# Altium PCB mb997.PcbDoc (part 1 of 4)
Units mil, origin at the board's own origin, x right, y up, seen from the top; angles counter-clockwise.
Board outline 2598.43 x 3818.9 mil, 2 copper layers (Top, Bottom), stack 62.402 mil thick; 205 components, 190 nets, 761 pads, 492 vias.
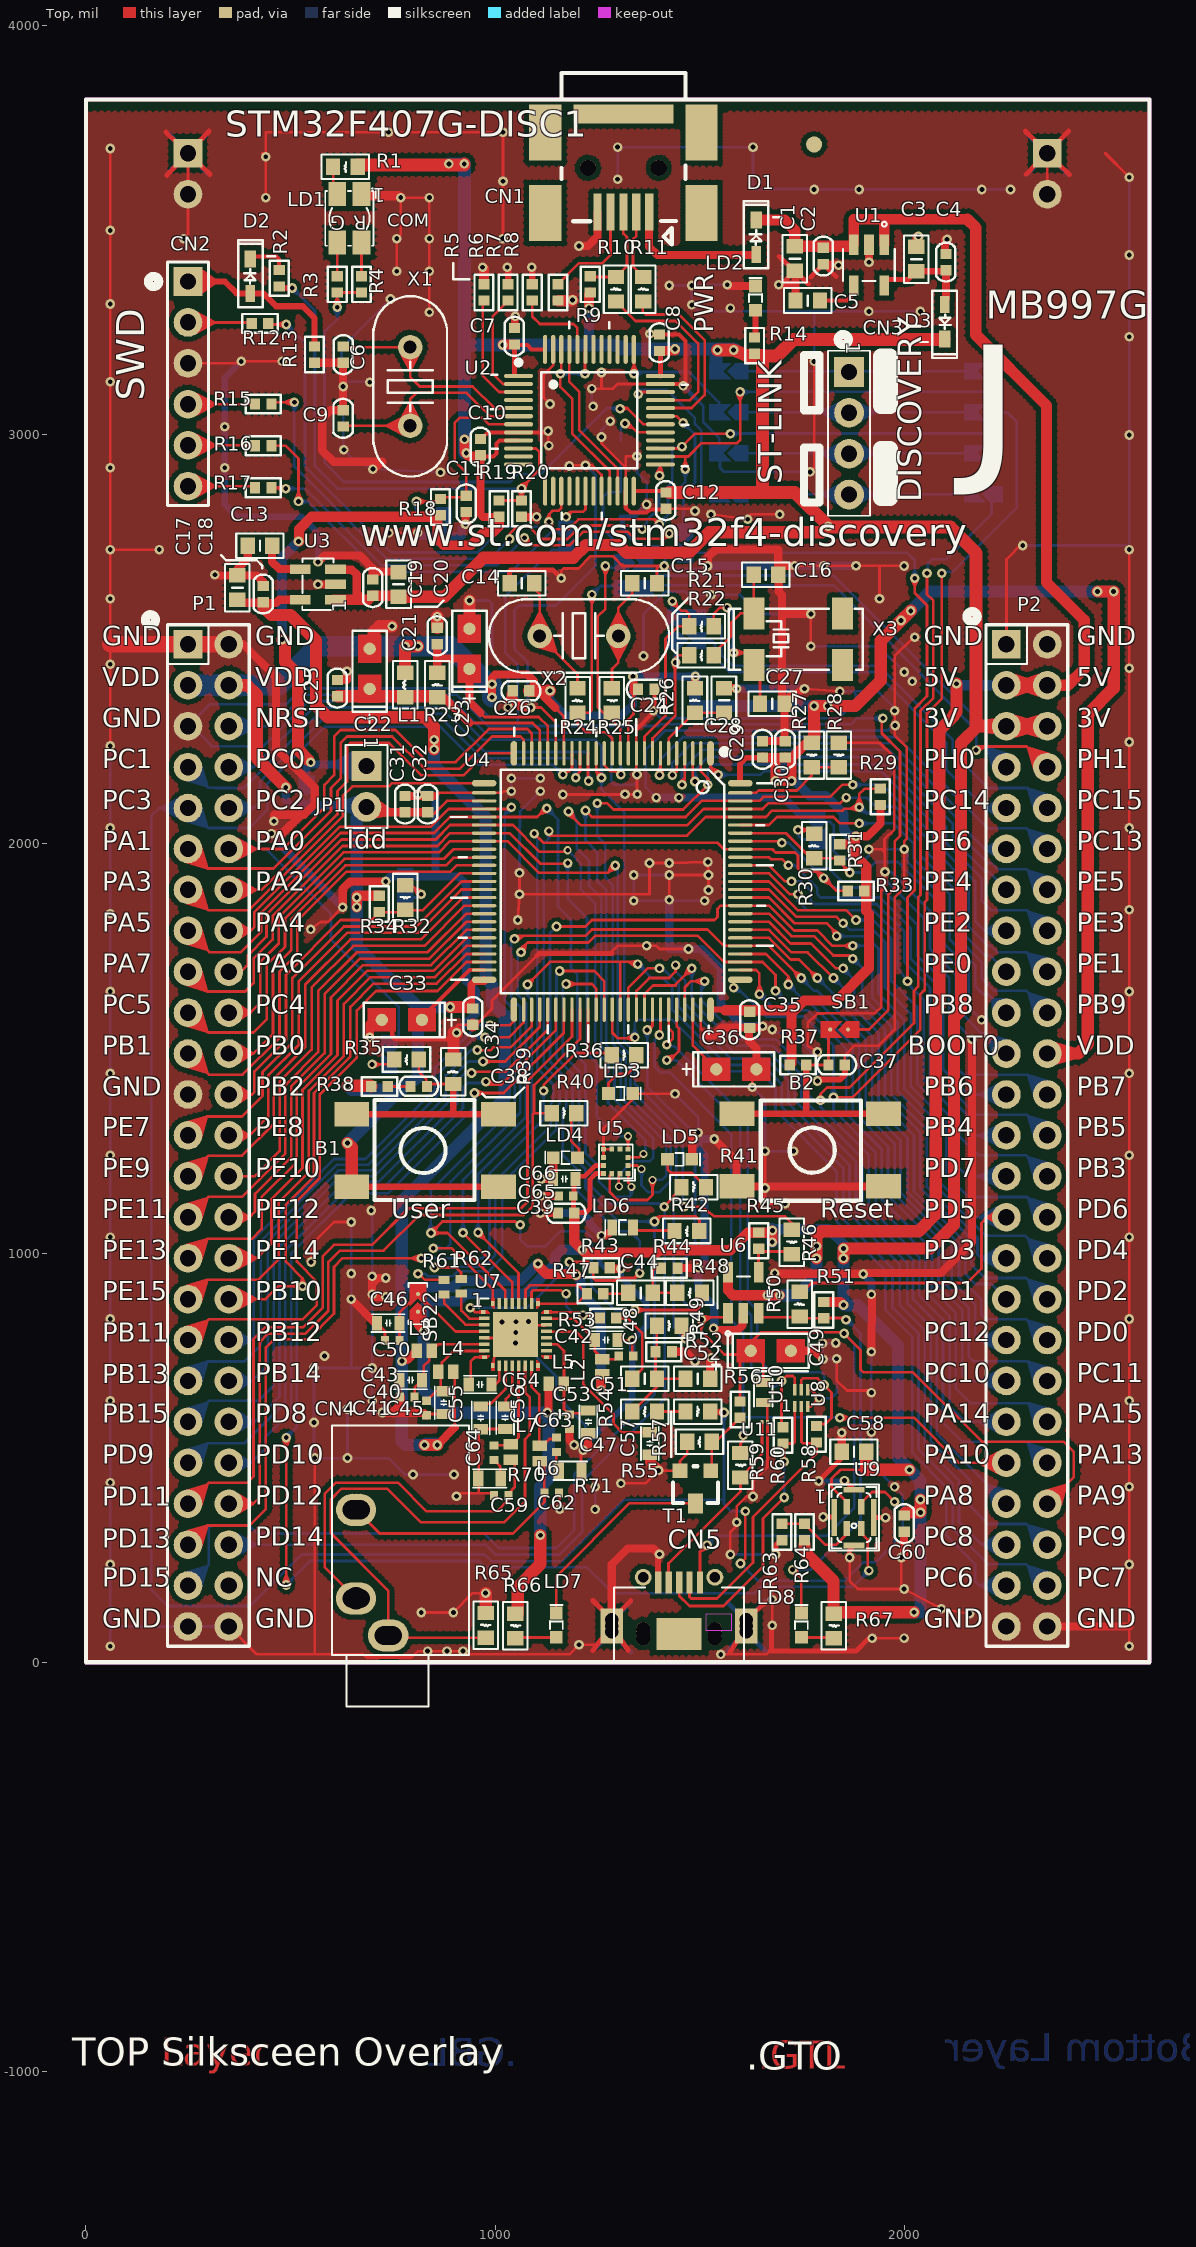
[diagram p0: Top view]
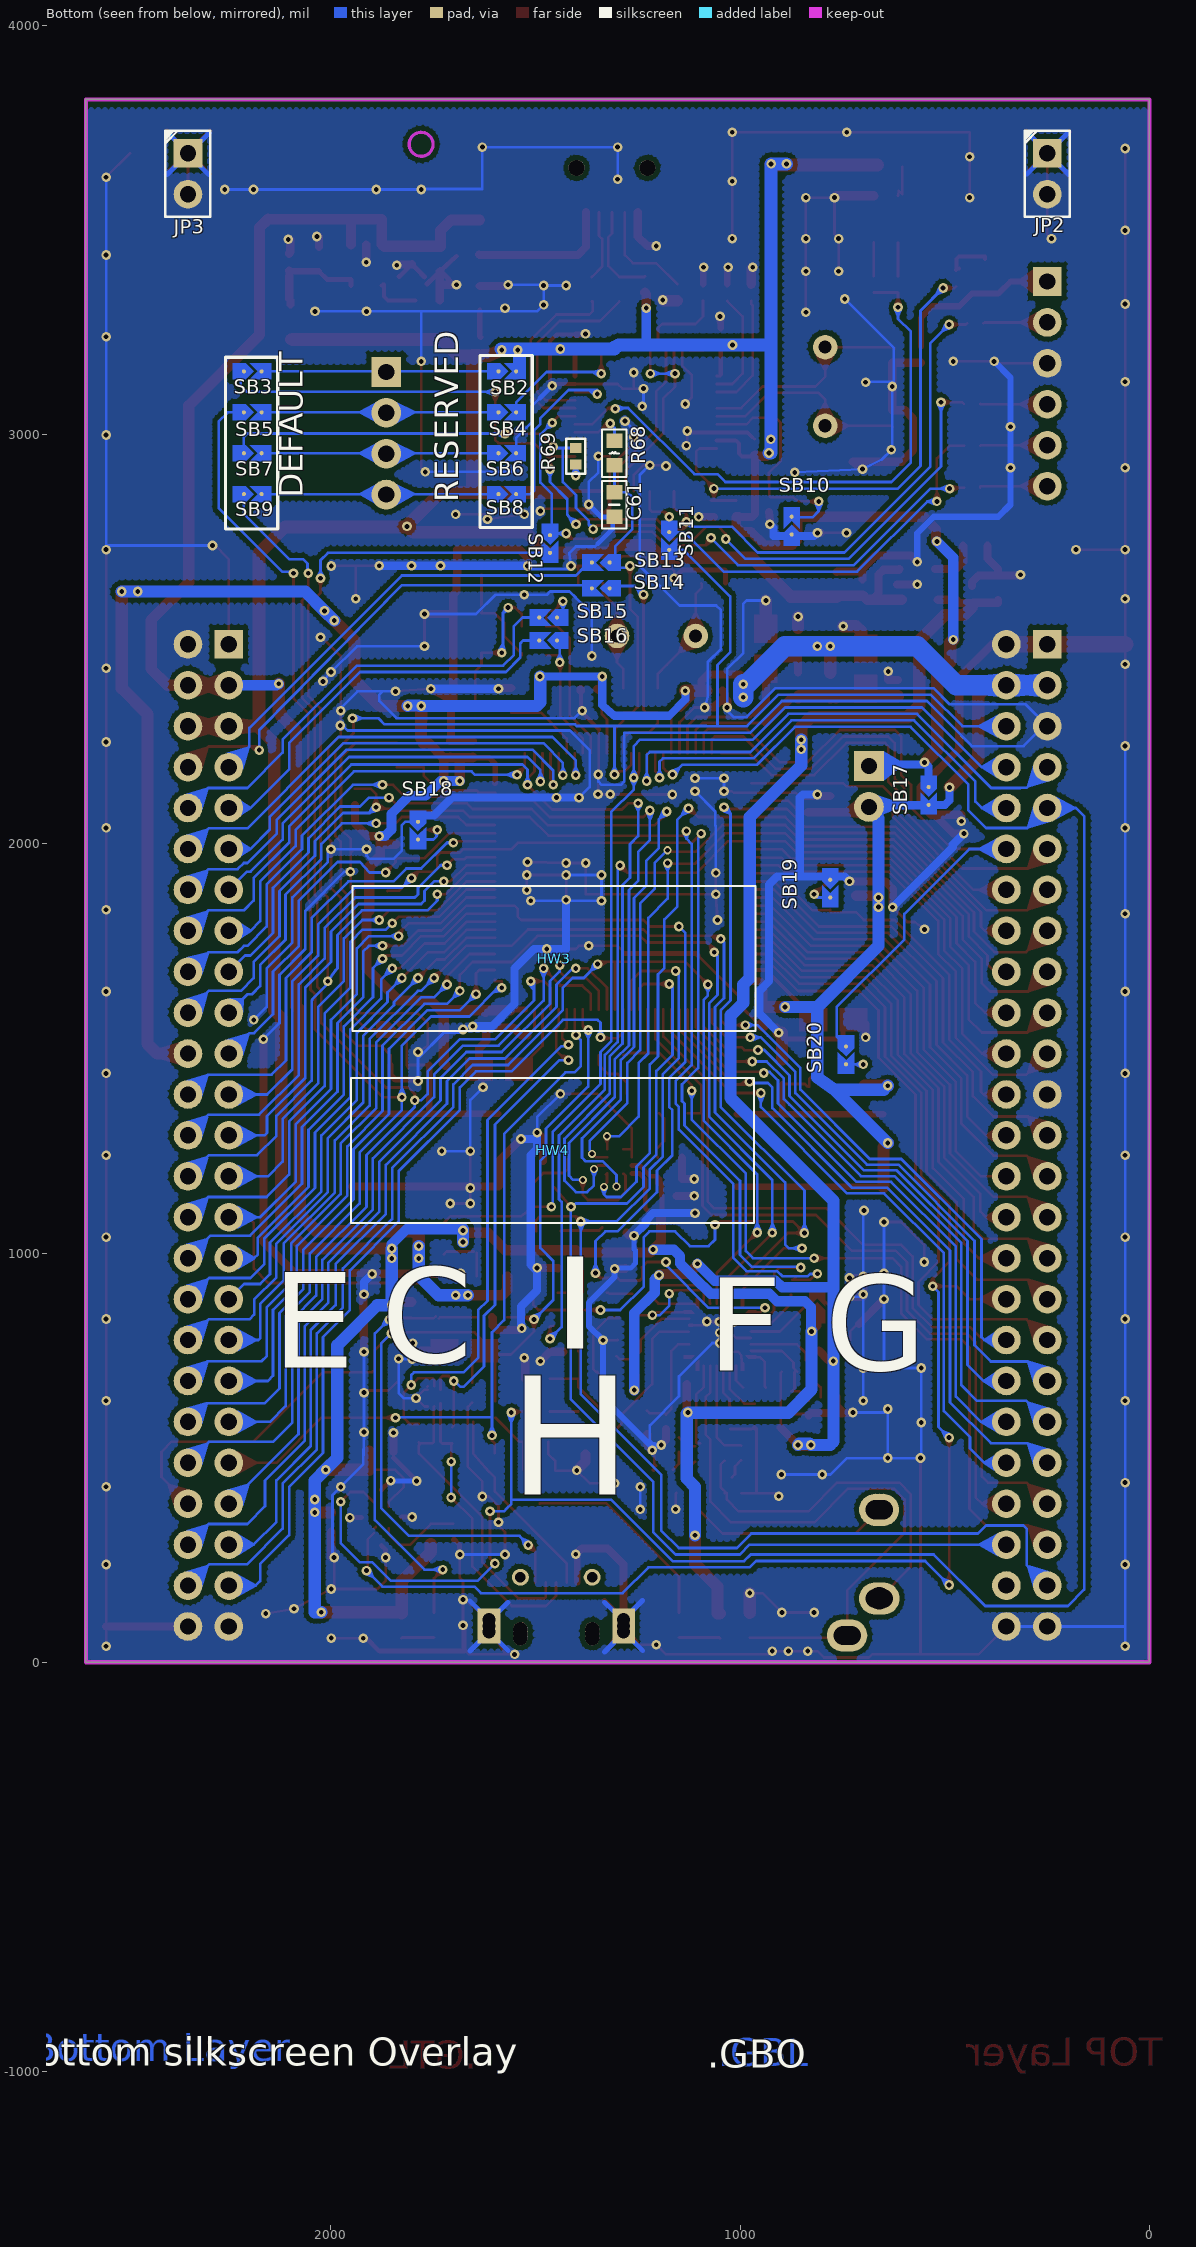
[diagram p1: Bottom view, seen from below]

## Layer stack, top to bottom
Solder Mask Top: solder mask 0.7874, Solder Resist, Dk 3.5
Top: signal copper 0.689
Dielectric 1: dielectric 61.0236, FR-4, Dk 4.2
Bottom: signal copper 0.689
Solder Mask Bottom: solder mask 0.7874, Solder Resist, Dk 3.5

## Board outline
0,0 2598.43,0 2598.43,3818.9 0,3818.9

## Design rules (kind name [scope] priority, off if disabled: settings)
Clearance Clearance_U7 [InComponent('U7')] p1: gap=6 ignorepadtopadclearanceinfootprint=TRUE except(3.94: Arc-Arc Arc-Track Track-Track; 5.12: Arc-Via Track-Via; 7: Track-Region SMDPad-Region; 9.84: Via-Fill Via-Poly Via-Region; 10: Text-Text; 11.81: Arc-Fill Arc-Poly Arc-Region Track-Fill Track-Poly; 12: SMDPad-Fill SMDPad-Poly THPad-Fill THPad-Poly THPad-Region Fill-Fill Fill-Poly Fill-Region Poly-Poly Poly-Region Region-Region)
Clearance Clearance_U5 [IsPad vs IsTrack] p2: gap=6 ignorepadtopadclearanceinfootprint=TRUE except(4.72: Arc-SMDPad Track-SMDPad; 10: Text-Text; 12: Arc-Fill Arc-Poly Arc-Region Track-Fill Track-Poly Track-Region SMDPad-Fill SMDPad-Poly SMDPad-Region THPad-Fill THPad-Poly THPad-Region Via-Fill Via-Poly Via-Region Fill-Fill Fill-Poly Fill-Region Poly-Poly Poly-Region Region-Region)
Clearance Clearance_CN5 [IsPad and ((Name = 'CN5-6') or (Name = 'CN5-6/2') or (Name = 'CN5-6/3') or (Name = 'CN5-6/4') or (Name = 'CN5-6/5') or (Name = 'CN5-6/6') or (Name = 'CN1-6') or (Name = 'CN1-7'))] p3: gap=6 ignorepadtopadclearanceinfootprint=TRUE except(5.98: Arc-Fill Arc-Poly Arc-Region Track-Fill Track-Poly Track-Region SMDPad-Fill SMDPad-Poly SMDPad-Region THPad-Fill THPad-Poly THPad-Region Via-Fill Via-Poly Via-Region Fill-Fill Fill-Poly Fill-Region Poly-Poly Poly-Region Region-Region; 10: Text-Text)
Clearance Clearance_JUMPER [HasFootprint('JUMPER') or HasFootprint('SOLDER-BRIDGE_R0603-0R') vs (HasFootprint('JUMPER')or HasFootprint('SOLDER-BRIDGE_R0603-0R') or IsTrack) and not InPolygon] p4: gap=6 ignorepadtopadclearanceinfootprint=FALSE except(5.91: Arc-Fill Arc-Poly Arc-Region Track-Fill Track-Poly Track-Region SMDPad-Fill SMDPad-Poly SMDPad-Region THPad-Fill THPad-Poly THPad-Region Via-Fill Via-Poly Via-Region Fill-Fill Fill-Poly Fill-Region Poly-Poly Poly-Region Region-Region; 10: Text-Text)
Clearance "Clearance - Default - DEFAULT- SMD" [IsVia vs IsSMTPin] p5 off: gap=6 ignorepadtopadclearanceinfootprint=FALSE
Clearance "Clearance - Default - DEFAULT - Via" [IsVia vs IsVia] p6 off: gap=6 ignorepadtopadclearanceinfootprint=FALSE
Clearance "Clearance - Default - DEFAULT - Net" [All] p7: gap=6 ignorepadtopadclearanceinfootprint=TRUE except(3.94: Arc-Arc Arc-Track Track-Track; 5.12: Arc-Via Track-Via; 9.84: Via-Fill Via-Poly Via-Region; 10: SMDPad-Region Text-Text; 11.81: Arc-Fill Arc-Poly Arc-Region Track-Fill Track-Poly Track-Region; 12: SMDPad-Fill SMDPad-Poly THPad-Fill THPad-Poly THPad-Region Fill-Fill Fill-Poly Fill-Region Poly-Poly Poly-Region Region-Region)
ComponentClearance "ComponentClearance - Default - DEFAULT" [All] p1: gap=6 collisioncheckmode=3 verticalgap=10 showdistances=FALSE
HoleToHoleClearance HoleToHoleClearance_CN5-6 [IsPad and ((Name = 'CN5-6') or (Name = 'CN5-6/2') or (Name = 'CN5-6/3') or (Name = 'CN5-6/4') or (Name = 'CN5-6/5') or (Name = 'CN5-6/6')) vs IsPad and ((Name = 'CN5-6') or (Name = 'CN5-6/2') or (Name = 'CN5-6/3') or (Name = 'CN5-6/4') or (Name = 'CN5-6/5') or (Name = 'CN5-6/6'))] p1: gap=0 allowstackedmicrovias=TRUE
HoleToHoleClearance HoleToHoleClearance_CN5-0 [IsPad and ((Name = 'CN5-0') or (Name = 'CN5-0/2') or (Name = 'CN5-0/6') or (Name = 'CN5-0/7') or (Name = 'CN5-0/8') or (Name = 'CN5-0/9') or (Name = 'CN5-0/11')) vs IsPad and ((Name = 'CN5-0') or (Name = 'CN5-0/2') or (Name = 'CN5-0/6') or (Name = 'CN5-0/7') or (Name = 'CN5-0/8') or (Name = 'CN5-0/9') or (Name = 'CN5-0/11'))] p2: gap=0 allowstackedmicrovias=TRUE
HoleToHoleClearance HoleToHoleClearance_CN4-3 [IsPad and ((Name = 'CN4-3') or (Name = 'CN4-3/2') or (Name = 'CN4-3/3')) vs IsPad and ((Name = 'CN4-3') or (Name = 'CN4-3/2') or (Name = 'CN4-3/3'))] p3: gap=0 allowstackedmicrovias=TRUE
HoleToHoleClearance HoleToHoleClearance_CN4-2 [IsPad and ((Name = 'CN4-2') or (Name = 'CN4-2/2') or (Name = 'CN4-2/3')) vs IsPad and ((Name = 'CN4-2') or (Name = 'CN4-2/2') or (Name = 'CN4-2/3'))] p4: gap=0 allowstackedmicrovias=TRUE
HoleToHoleClearance HoleToHoleClearance_CN4-1 [IsPad and ((Name = 'CN4-1') or (Name = 'CN4-1/2') or (Name = 'CN4-1/3')) vs IsPad and ((Name = 'CN4-1') or (Name = 'CN4-1/2') or (Name = 'CN4-1/3'))] p5: gap=0 allowstackedmicrovias=TRUE
HoleToHoleClearance "HoleToHoleClearance - Default - DEFAULT" [All] p6: gap=0 allowstackedmicrovias=TRUE
MaxMinImpedance "Default Impedance" [All] p1: minimum=50.00 maximum=150.0
MinimumSolderMaskSliver [All] p1: minsoldermaskwidth=3.94
PlaneConnect "Default PlaneConnect" [All] p1: planeconnectstyle=Relief reliefexpansion=20 reliefentries=4 reliefconductorwidth=11.81 reliefairgap=10
PolygonConnect PolygonConnect_Noyé [IsPad And (Layer = 'MultiLayer') And (PadShape_AllLayers = 'Round')] p1: connectstyle=Direct reliefconductorwidth=10 reliefentries=4 polygonreliefangle="90 Angle" airgapwidth=10
PolygonConnect "PolygonConnect - Default Pad" [All] p2: thpad.connectstyle=NoConnect thpad.reliefconductorwidth=11.81 thpad.reliefentries=4 thpad.polygonreliefangle="45 Angle" thpad.airgapwidth=12 smdpad.connectstyle=NoConnect smdpad.reliefconductorwidth=7.87 smdpad.reliefentries=4 smdpad.polygonreliefangle="45 Angle" smdpad.airgapwidth=12 via.connectstyle=Direct via.reliefconductorwidth=11.81 via.reliefentries=4 via.polygonreliefangle="45 Angle" via.airgapwidth=10
RoomDefinition U_USB_OTG_FS [InComponentClass('U_USB_OTG_FS')] p1: confinementstyle=ConfineIn formatcopy=TRUE lockcomponents=FALSE outline -10660.35,-8968.15 -8660.35,-8968.15 -8660.35,-7968.15 -10660.35,-7968.15
RoomDefinition U_Top [InComponentClass('U_Top')] p2: confinementstyle=ConfineIn formatcopy=TRUE lockcomponents=FALSE outline -10660.35,-8968.15 -8660.35,-8968.15 -8660.35,-7968.15 -10660.35,-7968.15
RoomDefinition U_STM32Fx [InComponentClass('U_STM32Fx')] p3: confinementstyle=ConfineIn formatcopy=TRUE lockcomponents=FALSE outline -10660.35,-8968.15 -8660.35,-8968.15 -8660.35,-7968.15 -10660.35,-7968.15
RoomDefinition U_ST_LINK [InComponentClass('U_ST_LINK')] p4: confinementstyle=ConfineIn formatcopy=TRUE lockcomponents=FALSE outline -10660.35,-8968.15 -8660.35,-8968.15 -8660.35,-7968.15 -10660.35,-7968.15
RoomDefinition "U_IO Peripherals" [InComponentClass('U_IO Peripherals')] p5: confinementstyle=ConfineIn formatcopy=TRUE lockcomponents=FALSE outline -10660.35,-8968.15 -8660.35,-8968.15 -8660.35,-7968.15 -10660.35,-7968.15
RoomDefinition U_Audio [InComponentClass('U_Audio')] p6: confinementstyle=ConfineIn formatcopy=TRUE lockcomponents=FALSE outline -10660.35,-8968.15 -8660.35,-8968.15 -8660.35,-7968.15 -10660.35,-7968.15
RoutingLayers "RoutingLayers - Default - DEFAULT" [All] p1: top layer_v5=TRUE bottom layer_v5=TRUE
RoutingPriority "RoutingPriority - Default - DEFAULT" [All] p1: routingpriority=3
RoutingTopology "Default Routing Topology" [All] p1: topology=Shortest
RoutingVias "RoutingVias - Default - DEFAULT" [All] p1: holewidth=11.81 width=23.62 viastyle="Through Hole" minholewidth=11.81 minwidth=23.62 maxholewidth=11.81 maxwidth=23.62
SMDToCorner "SMDToCorner - Default - DEFAULT" [All] p1: distance=0
ShortCircuit ShortCircuit_1 [IsPad and ((Name = 'CN5-6/2') or (Name = 'CN5-6/3') or (Name = 'CN5-6/5') or (Name = 'CN5-6') or (Name = 'CN5-6/4') or (Name = 'CN5-6/6')) vs IsPad and ((Name = 'CN5-6/2') or (Name = 'CN5-6/3') or (Name = 'CN5-6/5') or (Name = 'CN5-6') or (Name = 'CN5-6/4') or (Name = 'CN5-6/6'))] p1: allowed=TRUE
ShortCircuit ShortCircuit_CN5 [IsPad and ((Name = 'CN5-0') or (Name = 'CN5-0/2') or (Name = 'CN5-0/6') or (Name = 'CN5-0/7') or (Name = 'CN5-0/8') or (Name = 'CN5-0/9') or (Name = 'CN5-0/11')) vs IsPad and ((Name = 'CN5-0') or (Name = 'CN5-0/2') or (Name = 'CN5-0/6') or (Name = 'CN5-0/7') or (Name = 'CN5-0/8') or (Name = 'CN5-0/9') or (Name = 'CN5-0/11'))] p2: allowed=TRUE
ShortCircuit ShortCircuit_U7 [IsPad and (Name = 'U7-0') vs IsVia and (Net = 'GND')] p3: allowed=TRUE
ShortCircuit [All] p4: allowed=FALSE
SolderMaskExpansion SolderMaskExpansion_Via [IsVia] p1: expansion=-39.37 istentingtop=FALSE
SolderMaskExpansion "SolderMaskExpansion from CAM settings" [All] p2: expansion=2 istentingtop=FALSE
SupplyNets "Schematic Supply Nets_10" [InNet('MICVDD')] p1: voltage=0.000
SupplyNets "Schematic Supply Nets_9" [InNet('CPVDD')] p2: voltage=0.000
SupplyNets "Schematic Supply Nets_8" [InNet('AVDD')] p3: voltage=0.000
SupplyNets "Schematic Supply Nets_7" [InNet('DBVDD')] p4: voltage=0.000
SupplyNets "Schematic Supply Nets_4" [InNet('DCVDD')] p5: voltage=0.000
SupplyNets "Schematic Supply Nets_6" [InNet('1V8')] p6: voltage=0.000
SupplyNets "Schematic Supply Nets_5" [InNet('3V')] p7: voltage=0.000
SupplyNets "Schematic Supply Nets_3" [InNet('VDD')] p8: voltage=0.000
SupplyNets "Schematic Supply Nets_2" [InNet('GND')] p9: voltage=0.000
SupplyNets "Schematic Supply Nets_1" [InNet('U5V')] p10: voltage=0.000
SupplyNets "Schematic Supply Nets" [InNet('5V')] p11: voltage=0.000
Width "Default Width" [All] p1: maxlimit=78.74 minlimit=6.5 preferedwidth=6.5
22 further rules are at their usual default settings.

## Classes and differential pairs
component class U_USB_OTG_FS: C49 CN5 LD7 LD8 R45 R46 R50 R51 R56 R57 R58 R59 R60 R66 R67 T1 U6 U8 U10 U11
component class U_STM32Fx: C14 C15 C16 C21 C22 C23 C24 C25 C26 C27 C28 C29 C30 C31 C32 C33 C34 C35 C36 L1 R21 R22 R23 R24 R25 R26 R27 R28 R29 R30 R31 R32 R33 R34 SB13 SB14 SB15 SB16 SB18 SB19 U4 X2 X3
component class U_ST_LINK: C1 C2 C3 C4 C5 C6 C7 C8 C9 C10 C11 C12 C13 C17 C18 C19 C20 C61 CN1 CN2 CN3 D1 D2 D3 JP1 JP2 JP3 LD1 LD2 R1 R2 R3 R4 R5 R6 R7 R8 R9 R10 R11 R12 R13 R14 R15 R16 R17 R18 R19 R20 R68 R69 SB2 SB3 SB4 SB5 SB6 SB7 SB8 SB9 SB10 SB11 SB12 SB17 U1 U2 U3 X1
component class U_IO_Peripherals: B1 B2 C37 C38 C39 C65 C66 LD3 LD4 LD5 LD6 R35 R36 R37 R38 R39 R40 R41 R42 SB1 SB20 U5
component class U_Audio: C40 C41 C42 C43 C44 C45 C46 C47 C48 C50 C51 C52 C53 C54 C55 C56 C57 C58 C59 C60 C62 C63 C64 CN4 L2 L3 L4 L5 L6 L7 R43 R44 R47 R48 R49 R52 R53 R54 R55 R61 R62 R63 R64 R65 R70 R71 SB22 U7 U9
component class U_Top: HW3 HW4 P1 P2

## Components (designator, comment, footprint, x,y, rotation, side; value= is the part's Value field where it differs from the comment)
B1 "SW-PUSH-CMS" SW4SMD 825.21,1250.9 r180 top
B2 "SW-PUSH-CMS" SW4SMD 1773.21,1250.9 r0 top
C1 "1µF_X5R_0603" 0603C 1732.24,3429.96 r90 top value=1uF
C2 "100nF" 0402C 1801.71,3436.4 r90 top
C3 "1µF_X5R_0603" 0603C 2029.21,3428.9 r90 top value=1uF
C4 "100nF" 0402C 2101.71,3421.4 r270 top
C5 "10nF_X7R_0603" 0603C 1763.74,3327.6 r0 top value=10nF
C6 "20pF" 0402C 628.41,3195.5 r90 top
C7 "100nF" 0402C 1047.24,3240.16 r270 top
C8 "100nF" 0402C 1401.57,3224.41 r270 top
C9 "20pF" 0402C 628.41,3039.5 r270 top
C10 "100nF" 0402C 963.81,2969.3 r270 top
C11 "100nF" 0402C 929.13,2830.71 r90 top
C12 "100nF" 0402C 1417.32,2838.58 r270 top
C13 "10nF_X7R_0603" 0603C 425.2,2728.35 r0 top value=10nF
C14 "20pF" 0603C 1065.21,2636.9 r0 top
C15 "20pF" 0603C 1365.21,2636.9 r180 top
C16 "6.8pF" 0603C 1661.42,2657.48 r0 top
C17 "1µF_X5R_0603" 0603C 370.08,2625.98 r90 top value=1uF
C18 "100nF" 0402C 433.07,2610.24 r270 top
C19 "100nF" 0402C 700.79,2625.98 r270 top
C20 "1µF_X5R_0603" 0603C 763.78,2633.86 r270 top value=1uF
C21 "100nF" 0402C 858.27,2507.87 r270 top
C22 "1uF" CASE-A 693.22,2427.55 r90 top
C23 "1uF" CASE-A 937.01,2476.38 r90 top
C24 "100nF" 0402C 1369.21,2377.9 r0 top
C25 "100nF" 0402C 614.52,2380.33 r270 top
C26 "100nF" 0402C 1062.99,2374.02 r0 top
C27 "6.8pF" 0603C 1677.17,2342.52 r0 top
C28 "1uF" 0603C 1559.06,2350.39 r90 top
C29 "100nF" 0402C 1653.36,2230.8 r270 top
C30 "100nF" 0402C 1708.45,2230.8 r270 top
C31 "100nF" 0402C 779.79,2097.01 r270 top
C32 "100nF" 0402C 834.88,2097.01 r270 top
C33 "2.2uF" CASE-A 771.92,1569.72 r180 top
C34 "100nF" 0402C 945.06,1577.59 r90 top
C35 "100nF" 0402C 1621.88,1569.72 r270 top
C36 "2.2uF" CASE-A 1589.21,1448.9 r0 top
C37 "100nF" 0402C 1834.37,1459.54 r180 top
C38 "100nF" 0402C 813.21,1406.9 r180 top
C39 "100nF" 0402C 1173.29,1097.52 r0 top
C40 "100nF" C0402 785.27,647.58 r0 top
C41 "100nF" C0402 832.56,621.31 r90 top
C42 "4.7uF" C0603 1271.05,787.58 r180 top
C43 "4.7uF" C0603 793.32,689.19 r0 top
C44 "1uF(X7R)" 0603C 1355.2,902.6 r0 top value=1uF
C45 "4.7uF" C0603 874.23,634.29 r90 top
C46 "4.7uF" C0603 738.58,828.78 r0 top
C47 "4.7uF" C0603 1227.68,587.4 r90 top
C48 "100nF" C0402 1319.81,748.01 r180 top
C49 "4.7uF" CASE-A 1673.5,760.98 r0 top
C50 "100nF" C0402 748.34,785.7 r0 top
C51 "1uF(X7R)" 0603C 1365.2,692.6 r0 top value=1uF
C52 "10nF" 0603C 1495.2,692.6 r0 top
C53 "100nF" C0402 1181.16,587.4 r90 top
C54 "2.2uF" C0603 963.23,678.6 r0 top
C55 "2.2uF" C0603 964.69,597.19 r90 top
C56 "2.2uF" C0603 1024.25,597.45 r90 top
C57 "4.7uF" C0603 1377.95,534.47 r90 top
C58 "10uF" 0603C 1876.71,514.12 r0 top
C59 "470pF" C0402 1015.07,407.38 r180 top
C60 "100nF" 0402C 1999.21,338.9 r90 top
C61 "20pF" 0603C 1307.08,2828.92 r270 bottom
C62 "470pF" C0402 1137.99,414.14 r0 top
C63 "100nF" C0402 1149.21,531.55 r90 top
C64 "100nF" C0402 997.33,512.17 r90 top
C65 "100nF" C0402 1173.2,1139.61 r0 top
C66 "10uF" C0603 1168.79,1180.99 r0 top
CN1 "UBF-MINI5-03" USB-MINI-B-SMD-A_ 1313.35,3651.61 r0 top
CN2 "Header 6" HEADER6$2F$2.54 249.21,3374.02 r270 top
CN3 "Jumper_Header 4x1 fitted 1-2_3-4" CON_SAMTEC_TSW-104-07-G-S 1864.66,3003.22 r270 top
CN4 "ST-225-02" PCBCOMPONENT_1$2F$2_new_ 699.21,218.9 r90 top
CN5 "475900001" USB-MICRO-AB_new 1449.21,194.9 r90 top value=47590-0001
D1 "BAT60JFILM" SOD323$2F$A 1637.76,3524.45 r270 top
D2 "BAT60JFILM" SOD323$2F$A 401.57,3429.13 r270 top
D3 "BAT60JFILM" SOD323$2F$A 2098.39,3233.11 r90 top
HW3 "STICKER_BOARD_CPN" STICKER_25X9_ 1454.71,1719.25 r180 bottom
HW4 "STICKER_BOARD_REF" STICKER_25X9_ 1458.2,1250.69 r180 bottom
JP1 "Jumper_Header 2x1 Fitted" CON_SAMTEC_TSW-102-07-G-S 685.35,2140.24 r270 top
JP2 "" SIP2$2F$2.54 249.21,3637.4 r180 bottom
JP3 "" SIP2$2F$2.54 2349.21,3637.4 r180 bottom
L1 "fcm1608-0603" 0603L 779.79,2388.2 r270 top value=100uH
L2 "10R @100MHz" IND_0402_MURATA_BLM15H_H0P5 1261.43,721.93 r90 top
L3 "10R @100MHz" IND_0402_MURATA_BLM15H_H0P5 826.43,761.32 r0 top
L4 "10R @100MHz" IND_0402_MURATA_BLM15H_H0P5 879.18,710.17 r180 top
L5 "10R @100MHz" IND_0402_MURATA_BLM15H_H0P5 1149.21,680.03 r0 top
L6 "10R @100MHz" IND_0402_MURATA_BLM15H_H0P5 1109.33,510.4 r270 top
L7 "10R @100MHz" IND_0402_MURATA_BLM15H_H0P5 1037.56,513.82 r270 top
LD1 "LD_BICOLOR_CMS_1" LED_BI-GR_HSMF-A201-A00J1 643.66,3528.39 r180 top
LD2 "LED_red" LED_0603_RED 1636.12,3333.17 r90 top
LD3 "LED_orange" LED_0603_ORANGE_H0P4 1306.46,1389.76 r0 top
LD4 "LED_green" LED_0603_GREEN 1171.42,1232.9 r180 top
LD5 "LED_red" LED_0603_RED 1450.83,1229.04 r0 top
LD6 "LED_blue" LED_0603_SMD-B_BLUE_H0P4 1311.26,1062.75 r180 top
LD7 "LED_green" LED_0603_GREEN 1149.21,90.55 r90 top
LD8 "LED_red" LED_0603_RED 1748.03,90.55 r90 top
P1 "Header 25X2" HEAD25X2$2F$2.54 299.21,1287.4 r270 top
P2 "Header 25X2" HEAD25X2$2F$2.54 2299.21,1287.4 r270 top
R1 "0R" 0603R 633.82,3654.37 r0 top value=0
R2 "100" 0402R 472.44,3381.89 r270 top
R3 "560R" 0402R 614.13,3366.97 r90 top value=560
R4 "560R" 0402R 673.19,3366.97 r90 top value=560
R5 "10K" 0402R 972.4,3347.28 r270 top
R6 "10K" 0402R 1031.46,3347.28 r270 top
R7 "100K" 0402R 1090.51,3347.28 r270 top
R8 "100K" 0402R 1153.5,3347.28 r270 top
R9 "1K5" 0402R 1232.24,3366.97 r270 top
R10 "0" 0603R 1295.24,3355.16 r270 top
R11 "0" 0603R 1362.17,3355.16 r270 top
R12 "22" 0402R 425.2,3271.65 r0 top
R13 "10K" 0402R 558.21,3195.5 r270 top
R14 "1K" 0402R 1633.82,3217.36 r270 top
R15 "22" 0402R 433.07,3074.8 r0 top
R16 "22" 0402R 433.07,2972.44 r0 top
R17 "22" 0402R 433.07,2870.08 r0 top
R18 "100K" 0402R 866.14,2822.83 r270 top
R19 "4.7K" 0402R 1009.21,2818.9 r90 top
R20 "4.7K" 0402R 1064.09,2818.9 r90 top
R21 "0" 0603R 1503.94,2531.5 r0 top
R22 "0" 0603R 1503.94,2460.63 r0 top
R23 "47" 0603R 858.49,2388.2 r270 top
R24 "220" 0603R 1201.21,2349.9 r270 top
R25 "0" 0603R 1285.21,2349.9 r90 top
R26 "[N/A]" 0603R 1488.19,2350.39 r270 top value=0
R27 "[N/A]" 0603R 1773.21,2216.9 r90 top value=0
R28 "0" 0603R 1839.21,2216.9 r90 top
R29 "4.7K" 0402R 1941.21,2114.9 r90 top
R30 "510" 0603R 1779.28,1994.7 r270 top
R31 "10K" 0402R 1842.24,1978.96 r90 top
R32 "510" 0603R 779.79,1868.78 r90 top
R33 "4.7K" 0402R 1881.59,1884.52 r180 top
R34 "10K" 0402R 716.83,1853.04 r270 top
R35 "330" 0603R 783.21,1472.9 r0 top
R36 "680" 0603R 1314.95,1483.15 r180 top
R37 "1K5" 0402R 1739.93,1459.54 r180 top
R38 "100" 0402R 717.21,1406.9 r180 top
R39 "220K" 0603R 897.21,1442.9 r270 top
R40 "510" 0603R 1168.04,1341.61 r180 top
R41 "680" 0603R 1485.21,1160.9 r180 top
R42 "680" 0603R 1468.21,1053.9 r0 top
R43 "10K" 0402R 1259.86,963.73 r0 top
R44 "100K" 0402R 1425.2,962.6 r0 top
R45 "10K" 0402R 1644.21,1030.24 r270 top
R46 "0" 0603R 1724.19,1026.69 r90 top
R47 "100" 0402R 1244.12,900.77 r180 top
R48 "0" 0603R 1475.2,902.6 r0 top
R49 "0" 0603R 1425.13,822.07 r180 top
R50 "0" 0603R 1743.81,875.06 r270 top
R51 "47K" 0402R 1802.76,860.62 r270 top
R52 "100K" 0402R 1411.71,758.9 r0 top
R53 "100" 0402R 1275.59,841.18 r180 top
R54 "1.2K" 0603R 1365.2,612.6 r0 top
R55 "0" 0603R 1495.2,612.6 r180 top
R56 "47K" 0402R 1598.27,617.45 r90 top
R57 "[N/A]" 0603R 1499.21,538.9 r0 top value=1K
R58 "22R" 0402R 1784.91,557.15 r270 top value=47K
R59 "0R" 0603R 1599.21,481.4 r90 top value=0
R60 "22R" 0402R 1703.33,554.49 r270 top value=47K
R61 "0R" R0402 874.82,916.14 r90 top
R62 "0R" R0402 917.33,918.9 r90 top
R63 "0" 0402R 1700.58,318.39 r90 top
R64 "0" 0402R 1755.67,318.39 r270 top
R65 "0" 0603R 976.54,90.16 r90 top
R66 "330" 0603R 1049.21,88.9 r90 top
R67 "620" 0603R 1827.64,88.9 r90 top
R68 "100" 0603R 1307.08,2954.84 r270 bottom
R69 "100" 0402R 1401.52,2946.97 r90 bottom
R70 "20R" R0603 986.27,449.09 r0 top
R71 "20R" R0603 1183.15,467.86 r180 top
SB1 "Circuit Breaker" JUMPER 1842.24,1546.11 r180 top
SB2 "Circuit Breaker" JUMPER 1570.83,3154.37 r180 bottom
SB3 "Circuit Breaker" JUMPER 2192.87,3154.37 r180 bottom
SB4 "Circuit Breaker" JUMPER 1570.83,3054.37 r180 bottom
SB5 "Circuit Breaker" JUMPER 2192.87,3054.37 r180 bottom
SB6 "Circuit Breaker" JUMPER 1570.83,2954.37 r180 bottom
SB7 "Circuit Breaker" JUMPER 2192.87,2954.37 r180 bottom
SB8 "Circuit Breaker" JUMPER 1570.83,2854.37 r180 bottom
SB9 "Circuit Breaker" JUMPER 2192.87,2854.37 r180 bottom
SB10 "Circuit Breaker" JUMPER 874.02,2775.59 r90 bottom
SB11 "Circuit Breaker" JUMPER 1173.21,2741.9 r270 bottom
SB12 "Circuit Breaker" JUMPER 1464.48,2734.48 r270 bottom
SB13 "Circuit Breaker" JUMPER 1338.56,2687.26 r0 bottom
SB14 "Circuit Breaker" JUMPER 1338.56,2624.3 r0 bottom
SB15 "Circuit Breaker" JUMPER 1467.21,2552.9 r0 bottom
SB16 "Circuit Breaker" JUMPER 1467.21,2496.9 r0 bottom
SB17 "Circuit Breaker" JUMPER 539.21,2118.9 r270 bottom
SB18 "Circuit Breaker" JUMPER 1787.15,2034.05 r270 bottom
SB19 "Circuit Breaker" JUMPER 779.79,1892.39 r270 bottom
SB20 "Circuit Breaker" JUMPER 741.21,1484.9 r270 bottom
SB22 "0R" SOLDER-BRIDGE_R0603-0R 811.27,876.13 r90 top
T1 "9013" SOT23 1489.21,428.9 r180 top value=MMBT9013
U1 "LD3985M33R" SOT-23-5L 1913.35,3414.21 r0 top
U2 "STM32F103CBT6TR" LQFP48$2F$0.5MM$5C$9X9B 1118.11,2862.2 r0 top
U3 "LD3985M18R" REG_SOT23-5L 566.93,2633.86 r90 top
U4 "STM32F407VGT6" QFP100-1414 1285.96,1907.95 r180 top
U5 "IIS2DLPC" ICC_LGA12_2X2_P050_H0P7 1294.7,1223.9 r180 top
U6 "STMPS2141STR" SOT-23-5L 1606.24,903.26 r180 top
U7 "WM8904CGEFL/RV" ICC_QFN32-EPAD_4X4_P040 1049.4,800.74 r270 top
U8 "ECMF2-40A100N6" ESD_UQFN-6L_1P45X1P4_P040 1747.77,645.51 r0 top
U9 "CMM-4030DT-261075L-TR" MIC_SAME-SKY_CMM-4030DT-261075-TR 1876.71,353.34 r180 top
U10 "ESDA7P120-1U1M" ESD_QFN1610_2N_1K_2A 1654.68,658.9 r270 top
U11 "ESDZV5H-1BU2" ESD-BI_ST0201_H0P24 1658.5,587.4 r0 top
X1 "8MHz" HC-49A 792.21,3117.5 r90 top
X2 "8MHz" HC-49A 1204.72,2507.87 r0 top
X3 "MC306-G-06Q-32.768 (manufacturer JFVNY)" MC306-CRYSTAL 1740.16,2500 r0 top

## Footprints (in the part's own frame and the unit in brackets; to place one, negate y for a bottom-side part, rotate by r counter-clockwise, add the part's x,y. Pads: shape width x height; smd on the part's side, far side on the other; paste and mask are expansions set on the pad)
0402C [mil]
  rect 25x27.56 smd: 1(-20,0) 2(20,0)
  silkscreen extent -48,-24 47,23
0402R [mil]
  rect 25x27.56 smd: 1(-20,0) 2(20,0)
  silkscreen extent -43,-23 43,23
0603C [mil]
  rect 35x40 smd: 1(-30,0) 2(30,0)
  silkscreen extent -58,-30 58,30
0603L [mil]
  rect 35x40 smd: 1(-30,0) 2(30,0)
  silkscreen extent -58,-30 58,30
0603R [mil]
  rect 35x40 smd: 1(-30,0) 2(30,0)
  silkscreen extent -58,-30 58,30
C0402 [mm]
  rect 0.51x0.56 smd mask+0.05: 1(-0.45,0) 2(0.45,0)
  body extent -0.5,-0.3 0.5,0.3, height 0.4
C0603 [mm]
  rect 0.64x0.89 smd mask+0.05: 1(-0.7,0) 2(0.7,0)
  silkscreen extent -1.05,-0.55 1.02,0.55, body extent -0.9,-0.5 0.9,0.5, height 1.4
CASE-A [mil]
  round 30 smd: 1(-49,0) 2(49,0)
  Top region: -83,-28 -15,-28 -15,28 -83,28
  Top region: 15,-28 83,-28 83,28 15,28
  Top pour cut-out: -95.08,39.37 95.08,39.37 95.08,-39.96 -95.08,-39.96
  silkscreen extent -105,-42 93,42
CON_SAMTEC_TSW-102-07-G-S [mm]
  rect 1.85x1.85 / inner round 1.85 / far side rect 1.85x1.85 hole 1 mask+0.05: 1(-1.27,0)
  round 1.85 hole 1 mask+0.05: 2(1.27,0)
  silkscreen extent -2.58,-1.3 2.58,1.3, body extent -2.67,-1.3 2.58,1.3, height 8.38
CON_SAMTEC_TSW-104-07-G-S [mm]
  rect 1.85x1.85 / inner round 1.85 / far side rect 1.85x1.85 hole 1 mask+0.05: 1(-3.81,0)
  round 1.85 hole 1 mask+0.05: 2(-1.27,0) 3(1.27,0) 4(3.81,0)
  silkscreen extent -5.12,-1.3 5.12,1.3, body extent -5.21,-1.37 5.18,1.37, height 8.38
ESD-BI_ST0201_H0P24 [mm] "MCD-04846"
  rect 0.187x0.225 smd paste+0 mask+0.05: 1(-0.169,0) 2(0.169,0)
  body extent -0.31,-0.16 0.31,0.16, height 0.27
ESD_QFN1610_2N_1K_2A [mm] "DFN, 2-Leads, Body 1.60x1.00mm"
  rect 0.55x0.9 smd mask+0.05: 1(-0.625,0) 2(0.625,0)
  silkscreen extent -1.02,-0.58 0.85,0.58, body extent -0.85,-0.55 0.85,0.55, height 0.6
ESD_UQFN-6L_1P45X1P4_P040 [mm] "MCD-03060"
  rect 0.2x0.7 smd mask+0.05: 1(-0.4,-0.525) 2(0,-0.525) 3(0.4,-0.525) 4(0.4,0.525) 5(0,0.525) 6(-0.4,0.525)
  body extent -0.72,-0.7 0.72,0.7, height 0.51
HC-49A [mil]
  round 60 hole 32: 1(-96.06,0) 2(96.06,0)
  silkscreen extent -220,-90 220,90
HEAD25X2$2F$2.54 [mil]
  rect 70x70 hole 40: 1(-1200,-50)
  round 70 hole 40: 2(-1200,50) 3(-1100,-50) 4(-1100,50) 5(-1000,-50) 6(-1000,50) 7(-900,-50) 8(-900,50) 9(-800,-50) 10(-800,50) 11(-700,-50) 12(-700,50) 13(-600,-50) 14(-600,50) 15(-500,-50) 16(-500,50) 17(-400,-50) 18(-400,50) 19(-300,-50) 20(-300,50) 21(-200,-50) 22(-200,50) 23(-100,-50) 24(-100,50) 25(0,-50) 26(0,50) 27(100,-50) 28(100,50) 29(200,-50) 30(200,50) 31(300,-50) 32(300,50) 33(400,-50) 34(400,50) 35(500,-50) 36(500,50) 37(600,-50) 38(600,50) 39(700,-50) 40(700,50) 41(800,-50) 42(800,50) 43(900,-50) 44(900,50) 45(1000,-50) 46(1000,50) 47(1100,-50) 48(1100,50) 49(1200,-50) 50(1200,50)
  silkscreen extent -1248,-101 1248,100
HEADER6$2F$2.54 [mil]
  rect 70x70 hole 40: 1(0,0)
  round 70 hole 40: 2(100,0) 3(200,0) 4(300,0) 5(400,0) 6(500,0)
  silkscreen extent -48,-50 548,50
ICC_LGA12_2X2_P050_H0P7 [mm] "MCD-01448"
  rect 0.325x0.3 smd mask+0.05: 1(-0.763,0.75) 2(-0.763,0.25) 3(-0.763,-0.25) 4(-0.763,-0.75) 7(0.763,-0.75) 8(0.763,-0.25) 9(0.763,0.25) 10(0.763,0.75)
  rect 0.3x0.325 smd mask+0.05: 5(-0.25,-0.762) 6(0.25,-0.762) 11(0.25,0.763) 12(-0.25,0.763)
  silkscreen extent -1.2,-1.05 1.05,1.2, body extent -1.05,-1.05 1.05,1.05, height 0.71
ICC_QFN32-EPAD_4X4_P040 [mm]
  rect 0.22x0.3 smd mask+0.05: 1(-1.4,-2) 8(1.4,-1.925) 17(1.4,1.925) 24(-1.4,1.925)
  rect 0.22x0.66 smd mask+0.05: 2(-1,-1.925) 3(-0.6,-1.925) 4(-0.2,-1.925) 5(0.2,-1.925) 6(0.6,-1.925) 7(1,-1.925) 18(1,1.925) 19(0.6,1.925) 20(0.2,1.925) 21(-0.2,1.925) 22(-0.6,1.925) 23(-1,1.925)
  rect 0.3x0.22 smd mask+0.05: 9(1.925,-1.4) 16(1.925,1.4) 25(-1.925,1.4) 32(-1.925,-1.4)
  rect 0.66x0.22 smd mask+0.05: 10(1.925,-1) 11(1.925,-0.6) 12(1.925,-0.2) 13(1.925,0.2) 14(1.925,0.6) 15(1.925,1) 26(-1.925,1) 27(-1.925,0.6) 28(-1.925,0.2) 29(-1.925,-0.2) 30(-1.925,-0.6) 31(-1.925,-1)
  rect 2.8x2.8 smd mask+0.05: 33(0,0)
  Top region: 1.29,-2.255 1.29,-1.595 1.35,-1.595 1.51,-1.755 1.51,-2.255
  Top region: -1.29,-2.255 -1.29,-1.595 -1.35,-1.595 -1.51,-1.755 -1.51,-2.255
  Top region: -2.255,-1.29 -1.595,-1.29 -1.595,-1.35 -1.755,-1.51 -2.255,-1.51
  Top region: -2.255,1.29 -1.595,1.29 -1.595,1.35 -1.755,1.51 -2.255,1.51
  Top region: 2.255,1.29 1.595,1.29 1.595,1.35 1.755,1.51 2.255,1.51
  Top region: 2.255,-1.29 1.595,-1.29 1.595,-1.35 1.755,-1.51 2.255,-1.51
  Top region: 1.29,2.255 1.29,1.595 1.35,1.595 1.51,1.755 1.51,2.255
  Top region: -1.29,2.255 -1.29,1.595 -1.35,1.595 -1.51,1.755 -1.51,2.255
  silkscreen extent -2.25,-2.25 -1.68,-1.68, body extent -2.01,-2.01 2,2.01, height 0.91
IND_0402_MURATA_BLM15H_H0P5 [mm] "MCD-01610"
  rect 0.65x0.9 smd mask+0.05: 1(-0.475,0) 2(0.475,0)
  body extent -0.53,-0.28 0.53,0.28, height 0.55
JUMPER [mil]
  round 10 smd: 1(-19.68,0) 2(23.62,0)
  Top region: -47.24,-19.69 -47.24,19.68 -15.75,19.68 3.94,0 -15.75,-19.69
  Top region: -5.91,19.68 13.78,0 -5.91,-19.69 47.24,-19.69 47.24,19.68
  Top pour cut-out: -59.06,31.5 59.06,31.5 59.06,-31.5 -59.06,-31.5
LED_0603_GREEN [mm]
  rect 0.8x0.8 smd mask+0.05: 1(-0.75,0) 2(0.75,0)
  silkscreen extent -0.25,-0.4 1.25,0.4, body extent -0.8,-0.4 0.8,0.4, height 0.6
LED_0603_ORANGE_H0P4 [mm]
  rect 0.8x0.8 smd mask+0.05: 1(-0.75,0) 2(0.75,0)
  silkscreen extent -0.25,-0.4 1.25,0.4, body extent -0.8,-0.4 0.79,0.4, height 0.4
LED_0603_RED [mm]
  rect 0.8x0.8 smd mask+0.05: 1(-0.75,0) 2(0.75,0)
  silkscreen extent -0.25,-0.4 1.25,0.4, body extent -0.8,-0.4 0.8,0.4, height 0.6
LED_0603_SMD-B_BLUE_H0P4 [mm]
  rect 0.6x1 smd mask+0.05: 1(-0.65,0) 2(0.65,0)
  silkscreen extent -0.23,-0.45 1.07,0.45, body extent -0.85,-0.45 0.85,0.45, height 0.5
LED_BI-GR_HSMF-A201-A00J1 [mm] "MCD-00051"
  rect 1.1x1.5 smd mask+0.05: 1(-0.75,-1.5) 2(-0.75,1.5) 3(0.75,1.5) 4(0.75,-1.5)
  silkscreen extent -1.65,-1.85 1.5,1.7, body extent -1.5,-1.85 1.5,1.85, height 2.1
LQFP48$2F$0.5MM$5C$9X9B [mil]
  oval 71x10.13 smd: 1(-61,281.06) 12(-61,64.52) 25(285.46,64.53) 36(285.46,281.06)
  oval 71x10 smd: 2(-61,261.38) 3(-61,241.69) 4(-61,222.01) 5(-61,202.32) 6(-61,182.64) 7(-61,162.95) 8(-61,143.27) 9(-61,123.58) 10(-61,103.9) 11(-61,84.21) 26(285.46,84.21) 27(285.46,103.9) 28(285.46,123.58) 29(285.46,143.27) 30(285.46,162.95) 31(285.46,182.64) 32(285.46,202.32) 33(285.46,222.01) 34(285.46,241.69) 35(285.46,261.38)
  oval 10.13x71 smd: 13(3.96,-0.43) 24(220.5,-0.43) 37(220.5,346.02) 48(3.96,346.02)
  oval 10x71 smd: 14(23.65,-0.43) 15(43.33,-0.43) 16(63.02,-0.43) 17(82.7,-0.43) 18(102.39,-0.43) 19(122.07,-0.43) 20(141.76,-0.43) 21(161.44,-0.43) 22(181.13,-0.43) 23(200.81,-0.43) 38(200.81,346.02) 39(181.13,346.02) 40(161.44,346.02) 41(141.76,346.02) 42(122.07,346.02) 43(102.39,346.02) 44(82.7,346.02) 45(63.02,346.02) 46(43.33,346.02) 47(23.65,346.02)
  silkscreen extent -129,-69 354,414
MC306-CRYSTAL [mm]
  rect 1.3x2 smd: 1(-2.75,-1.6) 2(2.75,-1.6) 3(2.75,1.6) 4(-2.75,1.6)
  silkscreen extent -4.3,-1.9 4,1.9
MIC_SAME-SKY_CMM-4030DT-261075-TR [mm]
  rect 0.4x0.95 smd paste+0 mask+0.05: 1(0.45,-0.675) 2(0.45,0.675) 3(-0.45,0.675) 4(-0.45,-0.675)
  rect 0.35x2.3 smd paste+0 mask+0.05: 5(-1.225,0) 5(1.225,0)
  rect 1.3x0.35 smd paste+0 mask+0.05: 5(0,1.725) 5(0,-1.725)
  silkscreen extent -1.55,-2.05 1.55,2.05, body extent -1.45,-1.95 1.45,1.95, height 1.03
PCBCOMPONENT_1$2F$2_new_ [mm]
  round 2 hole 1.2: 1(-3.9,-1.254) 1(-3.9,-1) 1(-3.9,-0.746) 2(-1.6,0.746) 2(-1.6,1.254) 3(3.9,0.746) 3(3.9,1) 3(3.9,1.235)
  round 2 hole 1.4: 2(-1.6,1)
  silkscreen extent -8.31,-6 9.15,2.5
QFP100-1414 [mil]
  oval 16x60 smd: 1(-240.16,-312.99) 25(240.16,-312.99) 51(240.16,312.99) 75(-240.16,312.99)
  oval 8x60 smd: 2(-216.54,-312.99) 3(-196.85,-312.99) 4(-177.17,-312.99) 5(-157.48,-312.99) 6(-137.8,-312.99) 7(-118.11,-312.99) 8(-98.43,-312.99) 9(-78.74,-312.99) 10(-59.06,-312.99) 11(-39.37,-312.99) 12(-19.68,-312.99) 13(0,-312.99) 14(19.68,-312.99) 15(39.37,-312.99) 16(59.06,-312.99) 17(78.74,-312.99) 18(98.43,-312.99) 19(118.11,-312.99) 20(137.8,-312.99) 21(157.48,-312.99) 22(177.17,-312.99) 23(196.85,-312.99) 24(216.54,-312.99) 52(216.54,312.99) 53(196.85,312.99) 54(177.17,312.99) 55(157.48,312.99) 56(137.8,312.99) 57(118.11,312.99) 58(98.43,312.99) 59(78.74,312.99) 60(59.06,312.99) 61(39.37,312.99) 62(19.68,312.99) 63(0,312.99) 64(-19.68,312.99) 65(-39.37,312.99) 66(-59.06,312.99) 67(-78.74,312.99) 68(-98.43,312.99) 69(-118.11,312.99) 70(-137.8,312.99) 71(-157.48,312.99) 72(-177.17,312.99) 73(-196.85,312.99) 74(-216.54,312.99)
  oval 60x16 smd: 26(312.99,-240.16) 50(312.99,240.16) 76(-312.99,240.16) 100(-312.99,-240.16)
  oval 60x8 smd: 27(312.99,-216.54) 28(312.99,-196.85) 29(312.99,-177.17) 30(312.99,-157.48) 31(312.99,-137.8) 32(312.99,-118.11) 33(312.99,-98.43) 34(312.99,-78.74) 35(312.99,-59.06) 36(312.99,-39.37) 37(312.99,-19.69) 38(312.99,0) 39(312.99,19.68) 40(312.99,39.37) 41(312.99,59.06) 42(312.99,78.74) 43(312.99,98.43) 44(312.99,118.11) 45(312.99,137.8) 46(312.99,157.48) 47(312.99,177.17) 48(312.99,196.85) 49(312.99,216.54) 77(-312.99,216.54) 78(-312.99,196.85) 79(-312.99,177.17) 80(-312.99,157.48) 81(-312.99,137.8) 82(-312.99,118.11) 83(-312.99,98.43) 84(-312.99,78.74) 85(-312.99,59.06) 86(-312.99,39.37) 87(-312.99,19.68) 88(-312.99,0) 89(-312.99,-19.69) 90(-312.99,-39.37) 91(-312.99,-59.06) 92(-312.99,-78.74) 93(-312.99,-98.43) 94(-312.99,-118.11) 95(-312.99,-137.8) 96(-312.99,-157.48) 97(-312.99,-177.17) 98(-312.99,-196.85) 99(-312.99,-216.54)
  silkscreen extent -393,-396 394,392
R0402 [mm]
  rect 0.51x0.7 smd mask+0.05: 1(-0.45,0) 2(0.45,0)
  body extent -0.52,-0.3 0.52,0.3, height 0.4
R0603 [mm]
  rect 0.64x1 smd mask+0.05: 1(-0.7,0) 2(0.7,0)
  silkscreen extent -1.05,-0.58 1.05,0.58, body extent -0.9,-0.5 0.9,0.5, height 0.56
REG_SOT23-5L [mm]
  rect 0.6x1.3 smd mask+0.05: 1(-0.95,-1.1) 2(0,-1.1) 3(0.95,-1.1) 4(0.95,1.1) 5(-0.95,1.1)
  silkscreen extent -1.6,-0.95 1.6,0.97, body extent -1.52,-1.25 1.52,1.25, height 1.1
SIP2$2F$2.54 [mil]
  rect 70x70 / inner round 70 / far side rect 70x70 hole 40: 1(0,50)
  round 70 hole 40: 2(0,-50)
  silkscreen extent -55,-105 55,105
SOD323$2F$A [mm]
  rect 1.06x0.6 smd: 1(2.14,0)
  rect 1.06x0.7 smd: 2(0,0)
  silkscreen extent -1.17,-0.76 3,0.76
SOLDER-BRIDGE_R0603-0R [mil]
  round 10 smd mask-99999: 1(-19.69,0)
  round 10 smd paste-393.7: 2(23.62,0)
  Top region: -5.91,19.68 13.78,0 -5.91,-19.68 47.24,-19.68 47.24,19.68 -5.91,19.68
  Top region: -47.24,-19.68 -47.24,19.68 -15.75,19.68 3.94,0 -15.75,-19.68 -47.24,-19.68
  silkscreen extent -50,-23 50,23, body extent -36,-20 36,20, height 22
SOT23 [mil]
  rect 36x36 smd: 1(-37.5,-39) 2(37.5,-39)
  rect 36x50 smd: 3(0,41)
  silkscreen extent -55,-50 55,40
SOT-23-5L [mil]
  rect 23.62x50 smd: 1(37.4,50) 2(0,50) 3(-37.4,50) 4(-37.4,-50) 5(37.4,-50)
  silkscreen extent -63,-39 63,106
STICKER_25X9_ [mil] "Sticker 25mm x 9mm"
  silkscreen extent -492,-177 492,177
SW4SMD [mil]
  rect 85x60 smd: 1(175.59,-88.19) 2(-182.68,-88.19) 3(175.59,88.98) 4(-182.68,88.98)
  silkscreen extent -124,-123 121,122
USB-MICRO-AB_new [mm]
  round 1.4 hole 0.83: 0(-3.055,4.175) 0(-3.055,-4.175) 0(-2.7,4.175) 0(-2.7,-4.175) 0(-2.315,4.175) 0(-2.315,-4.175)
  rect 2.2x1.4 hole 0.83: 0(-2.7,4.175) 0(-2.7,-4.175)
  round 1.05 hole 0.65: 0/3(0.325,-2.225) 0/4(0.325,2.225)
  rect 2x2.8 smd: 0/5(-3.2,0)
  rect 1.35x0.4 smd: 1(0,-1.3) 2(0,-0.65) 3(0,0) 4(0,0.65) 5(0,1.3)
  round 0.9 hole 0.9 unplated: 6(-2.9,-2.225) 6/2(-3.175,2.225) 6/3(-2.9,2.225) 6/4(-3.45,-2.225) 6/5(-3.45,2.225) 6/6(-3.175,-2.225)
  silkscreen extent -4.9,-4.03 -0.3,4.03
USB-MINI-B-SMD-A_ [mm]
  rect 0.508x2.3 smd: 1(1.597,-2.75) 2(0.797,-2.75) 3(-0.003,-2.75) 4(-0.803,-2.75) 5(-1.603,-2.75)
  round 1 hole 1 unplated: 6(2.194,0) 7(-2.2,0)
  rect 2x3.5 smd: 8(-4.853,-2.8) 9(4.847,-2.8) 10(4.847,2.2) 11(-4.853,2.2)
  rect 6.2x1.2 smd: 12(0,3.35)
  silkscreen extent -3.85,-4.76 3.85,5.9

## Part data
B1: library part SW-PUSH-CMS_NEW, "Non-Open Push-Button 0.1A 24V", Manuf_1=CHAU-HUA, Manuf_Part_1=CTSM-644B-V-T/R
B2: library part SW-PUSH-CMS_NEW, "Non-Open Push-Button 0.1A 24V", Manuf_1=CHAU-HUA, Manuf_Part_1=CTSM-644N-V-T/R
C1 C3 C17 C20: library part "CAP SMD 0603  X5R 1µF 25V 10%", "0603  X5R 1µF", Manuf_1=YAGEO, Manuf_Part_1=CC0603KRX5R7BB105, Rated voltage=25V, Temperature Max=+125°C, Temperature Min=-55°C, Tolerance=10%
C2 C4 C7 C8 C10 C11 C12 C18 C19 C21 C24 C25 C26 C29 C30 C31 C32 C34 C35: library part Cap, "Capacitor", Manuf_1=YAGEO, Manuf_Part_1=CC0402KRX7R7BB104
C5 C13: library part "CAP SMD 0603  X7R 10000PF 50V 10%", "0603  X7R 10NF", Manuf_1=YAGEO, Manuf_Part_1=CC0603KRX7R9BB103, Rated voltage=50V, Temperature Max=+125°C, Temperature Min=-55°C, Tolerance=10%
C6 C9: library part Cap, "Capacitor", Manuf_1=YAGEO, Manuf_Part_1=CC0402JRNPO9BN200
C14 C15: library part CAP, "Capacitor", Manuf_1=YAGEO, Manuf_Part_1=CC0603JRNPO9BN200
C16 C27 C38: library part CAP, "Capacitor"
C22 C23: library part "Cap Pol1", "Polarized Capacitor (Radial)", Manuf_1=AVX, Manuf_Part_1=TAJA105K016R
C28 C44 C51: library part CAP, "Capacitor", Manuf_1=YAGEO, Manuf_Part_1=CC0603KRX5R7BB105
C33 C36: library part "Cap Low ESR", "Low ESR Ceramic Capacitor (X7R)", Manuf_1=YAGEO, Manuf_Part_1=CC1206KKX7R7BB225
C37 C39 C60: library part CAP, "Capacitor", Manuf_1=YAGEO, Manuf_Part_1=CC0402KRX7R7BB104
C40 C41 C48 C50 C53 C63 C64 C65: library part CC0402KRX7R7BB104, "Capacitor, MLCC, 100nF, 16V, X7R, +/-10%, 0402, T=0.5mm"
C42 C43 C45 C46 C47 C57: library part CC0603KRX5R7BB475, "Capacitor, MLCC, 4.7uF, 16V, X5R, +/-10%, 0603, T=0.8mm"
C49: library part "Cap Pol1", "Polarized Capacitor (Radial)", Manuf_1=AVX, Manuf_Part_1=TAJA475K016R
C52: library part CAP, "Capacitor", Manuf_1=YAGEO, Manuf_Part_1=CC0603KRX7R9BB103
C54 C55 C56: library part CC0603KRX5R6BB225, "Capacitor, MLCC, 2.2uF, 10V, X5R, +/- 10%, 0603, T=0.8mm"
C58: library part CAP, "Capacitor", Manuf_1=YAGEO, Manuf_Part_1=CC0603KRX5R5BB106
C59 C62: library part CC0402JRNPO9BN471, "Capacitor, MLCC, 470pF, 50V, C0G/NP0, +/-5%, 0402, T=0.5mm"
C61: library part Cap, "Capacitor"
C66: library part CC0603KRX5R5BB106, "Capacitor, MLCC, 10uF, 6V3, X5R, +/-10%, 0603, T=0.8mm"
CN1: library part "USB-MINI-typeB connector_", Manuf_1=MTCONN
CN2: "Header, 6-Pin", Manuf_1=LYCN, Manuf_Part_1=313106S141116
CN4: library part ST-225-02_, "Connector Jack 35mm", Manuf_1="XIEJIA Electronics"
CN5: library part 475900001_, Manuf_1=Molex, Manuf_Part_1=47590-0001
D1 D2 D3: Manuf_1=STM
JP2 JP3: library part JP2, Manuf_1=LYCN, Manuf_Part_1=313102S141145
L1: library part Inductor, "Inductor", Manuf_1=Tai-tech, Manuf_Part_1=FCM1608KF-601T03
L2 L3 L4 L5 L6 L7: library part BLM15AX100SN1D, "Ferrite bead, 10R @100MHz, 1.74A, 0.015R, 0402"
P1 P2: "Header, 25-Pin, Dual row", Manuf_1=LYCN, Manuf_Part_1=313250S141145
R1 R10 R11 R26 R48 R49 R55 R65: library part res1, "Resistor", Manuf_1=YAGEO, Manuf_Part_1=RC0603JR-070RL
R2 R57 R64: library part res1, "Resistor"
R3 R4: library part res1, "Resistor, 560R, 0402, +/-1%, 1/16W", Manuf_1=YAGEO, Manuf_Part_1=RC0402FR-07560RL
R5 R6 R13 R31 R34 R43 R45: library part res1, "Resistor", Manuf_1=YAGEO, Manuf_Part_1=RC0402FR-0710KL
R7 R8 R18 R44 R52: library part res1, "Resistor", Manuf_1=YAGEO, Manuf_Part_1=RC0402FR-07100KL
R9 R37: library part res1, "Resistor", Manuf_1=YAGEO, Manuf_Part_1=RC0402FR-071K5L
R12 R15 R16 R17: library part res1, "Resistor", Manuf_1=YAGEO, Manuf_Part_1=RC0402FR-0722RL
R14: library part res1, "Resistor", Manuf_1=YAGEO, Manuf_Part_1=RC0402FR-071KL
R19 R20 R29 R33: library part res1, "Resistor", Manuf_1=YAGEO, Manuf_Part_1=RC0402FR-074K7L
R21 R22 R27: library part Res1, "Resistor"
R23: library part Res1, "Resistor", Manuf_1=YAGEO, Manuf_Part_1=RC0603FR-0747RL
R24: library part Res1, "Resistor", Manuf_1=YAGEO, Manuf_Part_1=RC0603FR-07220RL
R25 R28 R46 R50 R59: library part Res1, "Resistor", Manuf_1=YAGEO, Manuf_Part_1=RC0603JR-070RL
R30 R40: library part Res1, "Resistor", Manuf_1=YAGEO, Manuf_Part_1=RC0603FR-07510RL
R32: library part res1, "Resistor", Manuf_1=YAGEO, Manuf_Part_1=RC0603FR-07510RL
R35 R66: library part res1, "Resistor", Manuf_1=YAGEO, Manuf_Part_1=RC0603FR-07330RL
R36 R41 R42: library part Res1, "Resistor", Manuf_1=YAGEO, Manuf_Part_1=RC0603FR-07680RL
R38 R47 R53 R69: library part res1, "Resistor", Manuf_1=YAGEO, Manuf_Part_1=RC0402FR-07100RL
R39: library part res1, "Resistor", Manuf_1=YAGEO, Manuf_Part_1=RC0603FR-07220KL
R51 R56: library part res1, "Resistor", Manuf_1=YAGEO, Manuf_Part_1=RC0402FR-0747KL
R54: library part res1, "Resistor", Manuf_1=YAGEO, Manuf_Part_1=RC0603FR-071K2L
R58 R60: library part RC0402FR-0722RL, "Resistor, 22R, 0402, +/-1%, 1/16W"
R61 R62: library part RC0402JR-070RL, "Resistor, 0R, 0402, +/-5%, 1/16W"
R63: library part res1, "Resistor", Manuf_1=YAGEO, Manuf_Part_1=RC0402JR-070RL
R67: library part Res1, "Resistor", Manuf_1=YAGEO, Manuf_Part_1=RC0603FR-07620RL
R68: library part res1, "Resistor", Manuf_1=YAGEO, Manuf_Part_1=RC0603FR-07100RL
R70 R71: library part RC0603FR-0720RL, "Resistor, 20R, 0603, +/-1%, 1/10W"
SB22: library part SB_ON, "Resistor, 0R, SB0603, 5%, 0.1W"
T1: library part NPN_NEW, "NPN Bipolar Transistor", Manuf_1=unisonic, Manuf_Part_1=MMBT9013
U1: "Ultra low drop-low noise BiCMOS voltage, regulators low ESR capacitors compatible", Manuf_1=STM
U2: library part STM32F103CBT6, "Medium-density performance line ARM-based 32-bit MCU with 128KB Flash", Manuf_1=STM
U4: "STM32 Manta (STM32F407VGT6)", Manuf_1=STM
U5: library part IC_IIS2DLPC
U6: "Enhanced single channel power switches", Manuf_1=STM
U7: library part IC_WM8904CGEFL/RV
U9: library part IC_CMM-4030DT-261075-TR, "MEMS Microphone, Top port, -26 ±1 dB, 2V6"
U10: library part ESD-TRANSIL, "Diode, ESD TVS, 5V5, 1.5uA, 6V8, QFN1610"
U11: library part ESD-TRANSIL-BIDIR, "Diode, ESD TVS, 5V5, 50nA, 10V, 0201"
X1 X2: library part XTAL, "Crystal Oscillator", Manuf_1=jfvny, Manuf_Part_1=HC-49S-C20QSA-8.000MHZ
X3: library part MC306

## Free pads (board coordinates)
  round 20 on Mech16: 1(403.98,-1259.28) 1(2303.7,-1265.01)
  round 39.37 smd mask+0: ""(1779.21,3708.9)

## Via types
v1: diameter 23.62, hole 11.81, Top to Bottom, 485 vias
v2: diameter 19.68, hole 11.81, Top to Bottom, 7 vias

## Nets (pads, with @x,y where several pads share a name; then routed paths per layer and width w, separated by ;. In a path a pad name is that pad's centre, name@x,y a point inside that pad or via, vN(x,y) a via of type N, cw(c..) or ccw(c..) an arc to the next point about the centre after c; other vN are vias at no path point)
1V8: C17.1 C18.2 L2.1 L3.1 L4.1 U3.5 | length 3995.5
  Top w6.5: C17.1@370.08,2595.98 433.07,2595.98 C18.2@433.07,2590.24 ; v1(772.22,735.79) v1@775.49,739.07 ; L4.1@897.88,710.17 900.9,707.15 900.9,573.29 ; L2.1@1258.53,700.32 L2.1@1261.43,703.22
  Top w20: C17.1@370.08,2595.98 370.08,2588.58 C18.2@442.91,2588.58 ; C18.2@433.07,2578.74 C18.2@442.91,2588.58 ; U3.5@516.93,2596.46 472.44,2596.46 464.57,2588.58 C18.2@442.91,2588.58 ; v1@775.49,739.07 785.47,739.07 L3.1@807.73,761.32 ; v1(858.49,530.88) 900.9,573.29
  Top w25: v1(1104.41,973.6) 1104.41,970.08 1126.01,948.47 1195.7,948.47 v1(1198.24,945.93) ; v1(1258.53,664.91) L2.1@1258.53,700.32
  Top w30: C18.2@433.07,2578.74 452.76,2559.06 500,2559.06 562.18,2496.87 562.18,2337.87 590.55,2309.5 827.01,2309.5 850.62,2285.89 v1(850.62,2254.41) v1(850.62,2230.8) ; v1(827.01,530.88) v1(858.49,530.88)
  Bottom w25: 771.92,916.14 897.48,916.14 913.58,932.25 1062.65,932.25 v1@1104.2,973.8 ; v1(1198.24,945.93) 1208.66,935.51 1208.66,903.15 1258.53,853.28 v1(1258.53,664.91)
  Bottom w30: v1(850.62,2254.41) v1(850.62,2230.8) 850.62,2191.45 976.54,2065.53 976.54,1672.03 992.28,1656.29 992.28,1610.9 1023.21,1580.9 1023.21,1379.19 771.92,1127.9 771.92,916.14 771.92,539.37 779.79,531.5 v1(827.01,530.88) 830.33,534.19 855.18,534.19 v1(858.49,530.88)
